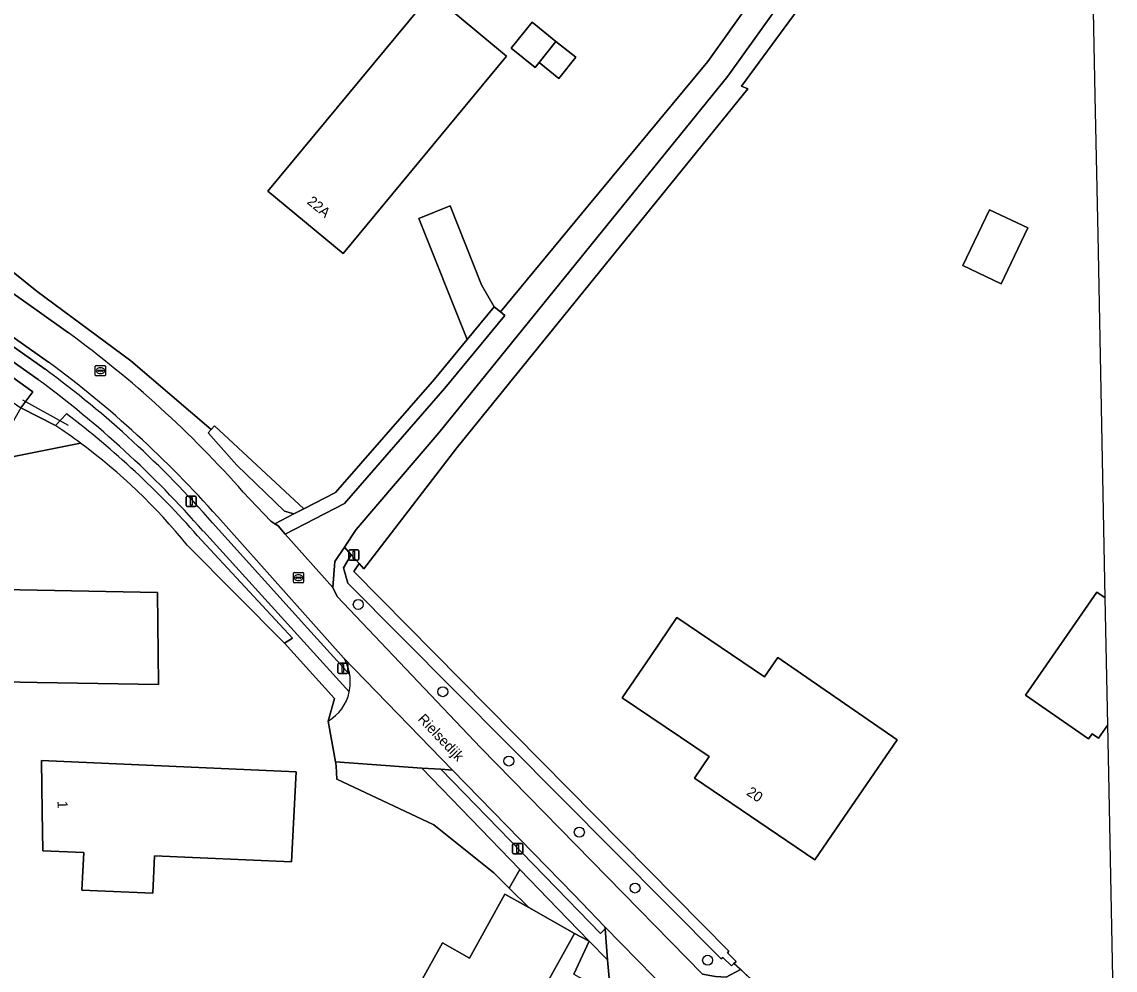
# Model space of a CAD drawing. Extents: x 163859 to 164644, y 379566 to 382155.
# Drawn here: x 164498.5 to 164605.3, y 381588.1 to 381680.8 of the extents above; entities that cross this region are included whole.
import ezdxf

# ---------------------------------------------------------------- set-up
doc = ezdxf.new("R2010")
doc.units = 0
for name, color, linetype in [('IMGEO_Boom', 7, 'Continuous'), ('IMGEO_Duiker', 7, 'Continuous'), ('IMGEO_Erf', 7, 'Continuous'), ('IMGEO_Fietspad_open', 7, 'Continuous'), ('IMGEO_Groenvoorziening', 7, 'Continuous'), ('IMGEO_Haag', 7, 'Continuous'), ('IMGEO_Lichtmast', 7, 'Continuous'), ('IMGEO_Loofbos', 7, 'Continuous'), ('IMGEO_Openbare_ruimte_label', 7, 'Continuous'), ('IMGEO_Pand', 7, 'Continuous'), ('IMGEO_Pand_nummerreeks', 7, 'Continuous'), ('IMGEO_Rijbaan_lokaal_gesloten', 7, 'Continuous'), ('IMGEO_Rijbaan_lokaal_halfverhard', 7, 'Continuous'), ('IMGEO_Rioolput', 7, 'Continuous'), ('IMGEO_Verkeersbordpaal', 7, 'Continuous'), ('IMGEO_Voetpad_open', 7, 'Continuous'), ('IMGEO_Waterloop', 7, 'Continuous')]:
    doc.layers.add(name, color=color, linetype=linetype)

msp = doc.modelspace()

# ---------------------------------------------------------------- linework, layer by layer
at = {"layer": 'IMGEO_Boom'}
for centre in [(164531.36, 381623.88), (164539.61, 381615.35), (164546.07, 381608.57), (164552.95, 381601.62), (164558.39, 381596.16), (164565.48, 381589.1)]:
    msp.add_circle(centre, 0.489, dxfattribs=at)
at = {"layer": 'IMGEO_Duiker'}
for points in [[(164503.07, 381641.38), (164498.6, 381643.85)], [(164571.59, 381585.44), (164568.07, 381588.81)]]:
    msp.add_lwpolyline(points, dxfattribs=at)
at = {"layer": 'IMGEO_Erf'}
for points in [[(164605.28, 381575.7), (164604.65, 381607.33), (164604.56, 381612.11), (164603.65, 381610.81), (164603.04, 381611.23), (164602.69, 381610.73), (164596.53, 381615), (164603.51, 381625.08), (164604.31, 381624.53), (164603.61, 381660.01), (164603.34, 381673.58), (164602.68, 381706.7)], [(164460.51, 381684.89), (164470.41, 381677.43), (164474.4, 381674.42), (164486.92, 381664.98), (164500, 381654.46), (164509.16, 381647.67), (164516.98, 381640.96), (164517.33, 381641.34), (164526.03, 381633.22), (164529.15, 381634.83), (164538.79, 381645.9), (164541.99, 381649.77), (164537.26, 381661.6), (164540.32, 381662.83), (164543.41, 381655.11), (164544.64, 381652.97), (164545.26, 381652.47), (164553.79, 381662.79), (164565.5, 381676.94), (164583.03, 381701.54)], [(164584.37, 381695.76), (164568.78, 381674.53), (164569.41, 381674.27), (164540.99, 381639.17), (164531.9, 381627.37), (164531.45, 381627.87), (164530.94, 381627.08), (164567.56, 381589.98), (164567.41, 381589.82), (164568.26, 381588.99), (164568.04, 381588.78), (164568.68, 381588.2), (164571.4, 381585.74)], [(164504.24, 381639.64), (164497.72, 381638.34), (164491.56, 381625.42), (164500, 381625.26), (164511.74, 381625.03), (164511.85, 381616.05), (164500, 381616.26), (164491.64, 381616.41), (164491.64, 381607.59), (164473.79, 381606.76), (164452.07, 381605.75)], [(164537.14, 381586.42), (164539.57, 381590.79), (164542.21, 381589.32), (164545.68, 381595.56), (164548.03, 381594.24), (164546.1, 381596.15), (164544.61, 381597.64), (164538.75, 381602.33), (164529.28, 381606.81), (164529.21, 381608.09), (164529.15, 381608.49), (164528.41, 381612.47), (164529.03, 381614.69), (164524.17, 381620.08), (164514.65, 381629.66)], [(164552.41, 381587.73), (164553.92, 381590.97), (164552.48, 381591.73), (164542.86, 381574.41)]]:
    msp.add_lwpolyline(points, dxfattribs=at)
for points in [[(164545.84, 381677.45), (164529.89, 381658.17), (164522.53, 381664.27), (164538.51, 381683.58)], [(164550.67, 381678.91), (164552.61, 381677.35), (164550.96, 381675.29), (164549.02, 381676.84), (164548.64, 381676.37), (164546.3, 381678.24), (164548.33, 381680.78)], [(164593.01, 381662.45), (164596.74, 381660.67), (164594.14, 381655.22), (164590.41, 381656.99)], [(164584, 381610.64), (164578.77, 381603.04), (164575.94, 381598.92), (164564.21, 381606.9), (164565.63, 381609), (164557.14, 381614.74), (164559.95, 381618.88), (164562.46, 381622.6), (164571.05, 381616.79), (164572.34, 381618.7)], [(164511.3, 381595.66), (164504.37, 381595.96), (164504.54, 381599.63), (164500.55, 381599.81), (164500.49, 381603.61), (164500.42, 381608.61), (164525.3, 381607.51), (164524.84, 381598.73), (164511.47, 381599.32)]]:
    msp.add_lwpolyline(points, close=True, dxfattribs=at)
msp.add_arc((164470.2, 381593.71), 57.17, 38.9591, 53.4562, dxfattribs=at)
at = {"layer": 'IMGEO_Fietspad_open'}
msp.add_lwpolyline([(164555.48, 381592.17), (164555.02, 381591.73), (164551.82, 381595.01), (164539.43, 381607.77), (164537.57, 381607.88), (164547.15, 381597.97), (164550.86, 381594.13), (164553.92, 381590.97), (164555.7, 381589.13)], close=True, dxfattribs=at)
at = {"layer": 'IMGEO_Groenvoorziening'}
for points in [[(164590.11, 381705.69), (164589.35, 381706.24), (164585.06, 381700.14), (164567.44, 381675.52), (164539.23, 381640.65), (164531.15, 381631.21), (164530, 381629.48), (164530.68, 381628.73), (164531.06, 381628.3), (164531.45, 381627.87), (164531.9, 381627.37), (164540.99, 381639.17), (164569.41, 381674.27), (164568.78, 381674.53), (164584.37, 381695.76), (164585.57, 381697.39), (164584.68, 381698)], [(164530, 381629.48), (164529.06, 381628.07), (164528.86, 381625.54), (164529.3, 381624.66), (164543.31, 381609.9), (164564.98, 381587.75), (164566.26, 381587.51), (164567.28, 381587.44), (164568.68, 381588.2), (164568.04, 381588.78), (164567.8, 381588.54), (164566.97, 381589.37), (164566.8, 381589.23), (164530.34, 381625.94), (164529.92, 381627.46), (164530.68, 381628.73)], [(164546.1, 381596.15), (164547.15, 381597.97), (164537.57, 381607.88), (164529.15, 381608.49), (164529.21, 381608.09), (164529.28, 381606.81), (164538.75, 381602.33), (164544.61, 381597.64)], [(164555.45, 381592.38), (164552.4, 381595.54), (164540.55, 381607.69), (164539.43, 381607.77), (164551.82, 381595.01), (164555.02, 381591.73), (164555.48, 381592.17)], [(164553.92, 381590.97), (164550.86, 381594.13), (164547.15, 381597.97), (164546.1, 381596.15), (164548.03, 381594.24), (164552.48, 381591.73)], [(164553.92, 381590.97), (164552.41, 381587.73), (164555.39, 381586.08), (164555.89, 381586.98), (164555.7, 381589.13)]]:
    msp.add_lwpolyline(points, close=True, dxfattribs=at)
for points in [[(164501.11, 381647.55), (164500, 381648.34), (164476.96, 381664.61), (164456.32, 381678.95), (164455.06, 381679.04), (164475.88, 381664.4), (164500, 381647.42), (164500.79, 381646.87)], [(164500.08, 381645.86), (164475.21, 381663.4), (164453.43, 381678.67)], [(164450.24, 381675.39), (164452.88, 381674.52), (164452.57, 381675.49), (164453.36, 381676.59), (164474.27, 381662.77), (164499.59, 381644.65), (164498.4, 381643.1), (164501.8, 381641.35), (164502.86, 381642.51)], [(164500, 381654.46), (164486.92, 381664.98), (164474.4, 381674.42), (164474.91, 381670.3), (164479.1, 381667.39), (164485.58, 381662.79), (164500, 381652.59), (164503.05, 381650.43)], [(164520.13, 381634.85), (164522.82, 381632.01), (164523.21, 381631.76), (164525.08, 381632.72), (164524.17, 381632.98), (164519.51, 381637.49), (164516.7, 381640.66), (164516.98, 381640.96), (164509.16, 381647.67), (164500, 381654.46)], [(164529.93, 381618.65), (164527, 381621.94), (164517.63, 381632.43)], [(164530.48, 381615.32), (164516.23, 381631.03)], [(164517.12, 381631.86), (164526.41, 381621.55), (164530.52, 381616.98)], [(164515.67, 381630.58), (164524.93, 381620.58), (164524.17, 381620.08), (164529.03, 381614.69), (164528.41, 381612.47)]]:
    msp.add_lwpolyline(points, dxfattribs=at)
for centre, radius, start, end in [((164440.03, 381564.16), 106.83, 41.429, 53.8516), ((164437.85, 381561.83), 106.54, 41.506, 53.5746), ((164438.25, 381562.31), 103.94, 41.3936, 53.5014), ((164438.41, 381562.58), 104.86, 41.3558, 53.4947), ((164450.37, 381573.34), 86.83, 41.2377, 52.812), ((164525.89, 381616.28), 4.69, 8.5904, 30.365), ((164526.31, 381616.18), 4.25, 299.5009, 348.3365)]:
    msp.add_arc(centre, radius, start, end, dxfattribs=at)
at = {"layer": 'IMGEO_Haag'}
for points in [[(164501.11, 381647.55), (164500, 381648.34), (164476.96, 381664.61), (164456.32, 381678.95), (164455.06, 381679.04), (164475.88, 381664.4), (164500, 381647.42), (164500.79, 381646.87)], [(164529.93, 381618.65), (164527, 381621.94), (164517.63, 381632.43)], [(164517.12, 381631.86), (164526.41, 381621.55), (164530.52, 381616.98)]]:
    msp.add_lwpolyline(points, dxfattribs=at)
msp.add_lwpolyline([(164555.45, 381592.38), (164552.4, 381595.54), (164540.55, 381607.69), (164539.43, 381607.77), (164551.82, 381595.01), (164555.02, 381591.73), (164555.48, 381592.17)], close=True, dxfattribs=at)
for centre, radius, start, end in [((164437.85, 381561.83), 106.54, 41.506, 53.5746), ((164438.41, 381562.58), 104.86, 41.3558, 53.4947), ((164525.89, 381616.28), 4.69, 8.5904, 30.365)]:
    msp.add_arc(centre, radius, start, end, dxfattribs=at)
at = {"layer": 'IMGEO_Lichtmast'}
for p, q in [((164514.55, 381633.55), (164514.55, 381634.35)), ((164514.55, 381634.35), (164514.55, 381633.55)), ((164514.65, 381634.45), (164515.44, 381634.45)), ((164515.44, 381634.45), (164514.65, 381634.45)), ((164515.54, 381634.35), (164515.54, 381633.55)), ((164515.54, 381633.55), (164515.54, 381634.35)), ((164515.44, 381633.45), (164514.65, 381633.45)), ((164514.65, 381633.45), (164515.44, 381633.45)), ((164529.46, 381618.12), (164530.25, 381618.12)), ((164530.25, 381618.12), (164529.46, 381618.12)), ((164529.36, 381617.22), (164529.36, 381618.02)), ((164529.36, 381618.02), (164529.36, 381617.22)), ((164530.25, 381617.12), (164529.46, 381617.12)), ((164529.46, 381617.12), (164530.25, 381617.12)), ((164530.35, 381618.02), (164530.35, 381617.22)), ((164530.35, 381617.22), (164530.35, 381618.02)), ((164546.43, 381599.6), (164546.43, 381600.4)), ((164546.43, 381600.4), (164546.43, 381599.6)), ((164546.53, 381600.5), (164547.32, 381600.5)), ((164547.32, 381600.5), (164546.53, 381600.5)), ((164547.42, 381600.4), (164547.42, 381599.6)), ((164547.42, 381599.6), (164547.42, 381600.4)), ((164547.32, 381599.5), (164546.53, 381599.5)), ((164546.53, 381599.5), (164547.32, 381599.5))]:
    msp.add_line(p, q, dxfattribs=at)
for points in [[(164514.97, 381634.32), (164515.12, 381634.32), (164515.12, 381633.57), (164514.97, 381633.57), (164514.97, 381634.32)], [(164529.78, 381618), (164529.93, 381618), (164529.93, 381617.25), (164529.78, 381617.25), (164529.78, 381618)], [(164546.85, 381600.38), (164547, 381600.38), (164547, 381599.63), (164546.85, 381599.63), (164546.85, 381600.38)]]:
    msp.add_lwpolyline(points, dxfattribs=at)
for centre, start, end in [((164514.65, 381634.35), 90, 180), ((164514.65, 381634.35), 90, 180), ((164515.44, 381634.35), 0, 90), ((164515.44, 381634.35), 360, 90), ((164514.65, 381633.55), 180, 270), ((164514.65, 381633.55), 180, 270), ((164515.44, 381633.55), 270, 0), ((164515.44, 381633.55), 270, 0), ((164529.46, 381618.02), 90, 180), ((164529.46, 381618.02), 90, 180), ((164530.25, 381618.02), 0, 90), ((164530.25, 381618.02), 360, 90), ((164529.46, 381617.22), 180, 270), ((164529.46, 381617.22), 180, 270), ((164530.25, 381617.22), 270, 0), ((164530.25, 381617.22), 270, 0), ((164546.53, 381600.4), 90, 180), ((164546.53, 381600.4), 90, 180), ((164547.32, 381600.4), 0, 90), ((164547.32, 381600.4), 360, 90), ((164546.53, 381599.6), 180, 270), ((164546.53, 381599.6), 180, 270), ((164547.32, 381599.6), 270, 0), ((164547.32, 381599.6), 270, 0)]:
    msp.add_arc(centre, 0.1, start, end, dxfattribs=at)
at = {"layer": 'IMGEO_Loofbos'}
msp.add_lwpolyline([(164501.8, 381641.35), (164498.4, 381643.1), (164483.66, 381617.04), (164473.55, 381613.91), (164473.69, 381609.8), (164473.79, 381606.76), (164491.64, 381607.59), (164491.64, 381616.41), (164491.56, 381625.42), (164497.72, 381638.34), (164504.24, 381639.64)], dxfattribs=at)
msp.add_arc((164470.8, 381594.55), 56.13, 53.4347, 56.4708, dxfattribs=at)
at = {"layer": 'IMGEO_Pand'}
for points in [[(164545.84, 381677.45), (164538.51, 381683.58), (164522.53, 381664.27), (164529.89, 381658.17)], [(164549.02, 381676.84), (164550.67, 381678.91), (164548.33, 381680.78), (164546.3, 381678.24), (164548.64, 381676.37)], [(164550.67, 381678.91), (164549.02, 381676.84), (164550.96, 381675.29), (164552.61, 381677.35)], [(164593.01, 381662.45), (164590.41, 381656.99), (164594.14, 381655.22), (164596.74, 381660.67)], [(164511.74, 381625.03), (164500, 381625.26), (164491.56, 381625.42), (164491.64, 381616.41), (164500, 381616.26), (164511.85, 381616.05)], [(164604.56, 381612.11), (164604.31, 381624.53), (164603.51, 381625.08), (164596.53, 381615), (164602.69, 381610.73), (164603.04, 381611.23), (164603.65, 381610.81)], [(164572.34, 381618.7), (164571.05, 381616.79), (164562.46, 381622.6), (164559.95, 381618.88), (164557.14, 381614.74), (164565.63, 381609), (164564.21, 381606.9), (164575.94, 381598.92), (164578.77, 381603.04), (164584, 381610.64)], [(164525.3, 381607.51), (164500.42, 381608.61), (164500.49, 381603.61), (164500.55, 381599.81), (164504.54, 381599.63), (164504.37, 381595.96), (164511.3, 381595.66), (164511.47, 381599.32), (164524.84, 381598.73)], [(164552.48, 381591.73), (164548.03, 381594.24), (164545.68, 381595.56), (164542.21, 381589.32), (164539.57, 381590.79), (164537.14, 381586.42), (164539.76, 381584.96), (164536.02, 381578.22), (164542.86, 381574.41)]]:
    msp.add_lwpolyline(points, close=True, dxfattribs=at)
at = {"layer": 'IMGEO_Rijbaan_lokaal_gesloten'}
for points in [[(164503.05, 381650.43), (164500, 381652.59), (164485.58, 381662.79), (164479.1, 381667.39), (164474.91, 381670.3), (164466.53, 381676.14), (164455.77, 381683.63), (164441.19, 381693.79), (164424.68, 381705.23)], [(164424.31, 381700.57), (164445.11, 381686.13), (164456.32, 381678.95), (164476.96, 381664.61), (164500, 381648.34), (164501.11, 381647.55)], [(164543.31, 381609.9), (164529.3, 381624.66), (164528.86, 381625.54), (164524.23, 381630.76), (164523.52, 381631.56), (164523.21, 381631.76), (164522.82, 381632.01), (164520.13, 381634.85)], [(164517.63, 381632.43), (164527, 381621.94), (164529.93, 381618.65), (164540.55, 381607.69), (164552.4, 381595.54), (164555.45, 381592.38), (164563.42, 381584.23)], [(164570.33, 381584.58), (164571.4, 381585.74), (164568.68, 381588.2), (164567.28, 381587.44), (164566.26, 381587.51), (164564.98, 381587.75), (164543.31, 381609.9)]]:
    msp.add_lwpolyline(points, dxfattribs=at)
for centre, radius, start, end in [((164440.03, 381564.16), 106.83, 41.429, 53.8516), ((164437.85, 381561.83), 106.54, 41.506, 53.5746)]:
    msp.add_arc(centre, radius, start, end, dxfattribs=at)
at = {"layer": 'IMGEO_Rijbaan_lokaal_halfverhard'}
msp.add_lwpolyline([(164567.44, 381675.52), (164585.06, 381700.14), (164583.03, 381701.54), (164565.5, 381676.94), (164553.79, 381662.79), (164545.26, 381652.47), (164545.68, 381652.11), (164539.82, 381645.02), (164530, 381633.75), (164524.23, 381630.76), (164528.86, 381625.54), (164529.06, 381628.07), (164530, 381629.48), (164531.15, 381631.21), (164539.23, 381640.65)], close=True, dxfattribs=at)
at = {"layer": 'IMGEO_Rioolput'}
for p, q in [((164505.67, 381646.29), (164505.67, 381647.15)), ((164505.75, 381647.22), (164506.6, 381647.22)), ((164506.16, 381647), (164506.19, 381647)), ((164506.68, 381647.15), (164506.68, 381646.29)), ((164506.6, 381646.22), (164505.75, 381646.22)), ((164505.93, 381646.71), (164505.93, 381646.73)), ((164506.37, 381646.68), (164505.97, 381646.68)), ((164505.98, 381646.76), (164506.37, 381646.76)), ((164506.18, 381646.44), (164506.16, 381646.44)), ((164506.42, 381646.73), (164506.42, 381646.71)), ((164525.02, 381626.07), (164525.02, 381626.92)), ((164525.09, 381626.99), (164525.95, 381626.99)), ((164525.51, 381626.77), (164525.53, 381626.77)), ((164526.02, 381626.92), (164526.02, 381626.07)), ((164525.95, 381625.99), (164525.09, 381625.99)), ((164525.28, 381626.49), (164525.28, 381626.5)), ((164525.32, 381626.54), (164525.72, 381626.54)), ((164525.72, 381626.45), (164525.32, 381626.45)), ((164525.53, 381626.21), (164525.5, 381626.21)), ((164525.76, 381626.5), (164525.76, 381626.49))]:
    msp.add_line(p, q, dxfattribs=at)
for points in [[(164505.67, 381646.29), (164505.67, 381647.15)], [(164505.75, 381647.22), (164506.6, 381647.22)], [(164506.68, 381647.15), (164506.68, 381646.29)], [(164506.6, 381646.22), (164505.75, 381646.22)], [(164525.02, 381626.07), (164525.02, 381626.92)], [(164525.09, 381626.99), (164525.95, 381626.99)], [(164526.02, 381626.92), (164526.02, 381626.07)], [(164525.95, 381625.99), (164525.09, 381625.99)]]:
    msp.add_lwpolyline(points, dxfattribs=at)
for centre, radius, start, end in [((164505.75, 381647.14), 0.0765, 91.552, 178.448), ((164505.75, 381647.14), 0.0765, 91.552, 178.448), ((164506.6, 381647.14), 0.0765, 1.552, 88.448), ((164506.6, 381647.14), 0.0765, 1.552, 88.448), ((164505.75, 381646.3), 0.0765, 181.552, 268.448), ((164505.75, 381646.3), 0.0765, 181.552, 268.448), ((164505.97, 381646.72), 0.0403, 85.8775, 175.7526), ((164505.97, 381646.71), 0.0366, 178.938, 274.7102), ((164506.38, 381646.72), 0.0386, 1.7309, 96.639), ((164506.37, 381646.72), 0.043, 264.8664, 352.4533), ((164506.6, 381646.3), 0.0765, 271.552, 358.448), ((164506.6, 381646.3), 0.0765, 271.552, 358.448), ((164525.1, 381626.92), 0.0765, 91.552, 178.448), ((164525.1, 381626.92), 0.0765, 91.552, 178.448), ((164525.94, 381626.92), 0.0765, 1.552, 88.448), ((164525.94, 381626.92), 0.0765, 1.552, 88.448), ((164525.1, 381626.07), 0.0765, 181.552, 268.448), ((164525.1, 381626.07), 0.0765, 181.552, 268.448), ((164525.32, 381626.5), 0.0403, 85.8775, 175.7526), ((164525.31, 381626.49), 0.0366, 178.938, 274.7102), ((164525.72, 381626.5), 0.0386, 1.7309, 96.639), ((164525.72, 381626.49), 0.043, 264.8664, 352.4533), ((164525.94, 381626.07), 0.0765, 271.552, 358.448), ((164525.94, 381626.07), 0.0765, 271.552, 358.448)]:
    msp.add_arc(centre, radius, start, end, dxfattribs=at)
for centre, major_axis, ratio, start_param, end_param in [((164506.16, 381646.72), (-0.387, 0.002), 0.722429, 4.712389, 7.853982), ((164506.19, 381646.72), (-0.39, 0.002), 0.717154, 1.570796, 4.712389), ((164525.51, 381626.49), (-0.387, 0.002), 0.722429, 4.712389, 7.853982), ((164525.53, 381626.49), (-0.39, 0.002), 0.717154, 1.570796, 4.712389)]:
    msp.add_ellipse(centre, major_axis=major_axis, ratio=ratio, start_param=start_param, end_param=end_param, dxfattribs=at)
at = {"layer": 'IMGEO_Verkeersbordpaal'}
for p, q in [((164530.43, 381628.3), (164530.43, 381629.1)), ((164530.43, 381629.1), (164530.43, 381628.3)), ((164530.53, 381629.2), (164531.32, 381629.2)), ((164531.32, 381629.2), (164530.53, 381629.2)), ((164531.42, 381629.1), (164531.42, 381628.3)), ((164531.42, 381628.3), (164531.42, 381629.1)), ((164531.32, 381628.2), (164530.53, 381628.2)), ((164530.53, 381628.2), (164531.32, 381628.2))]:
    msp.add_line(p, q, dxfattribs=at)
msp.add_lwpolyline([(164530.85, 381629.08), (164531, 381629.08), (164531, 381628.33), (164530.85, 381628.33), (164530.85, 381629.08)], dxfattribs=at)
for centre, start, end in [((164530.53, 381629.1), 90, 180), ((164530.53, 381629.1), 90, 180), ((164531.32, 381629.1), 0, 90), ((164531.32, 381629.1), 360, 90), ((164530.53, 381628.3), 180, 270), ((164530.53, 381628.3), 180, 270), ((164531.32, 381628.3), 270, 0), ((164531.32, 381628.3), 270, 0)]:
    msp.add_arc(centre, 0.1, start, end, dxfattribs=at)
at = {"layer": 'IMGEO_Voetpad_open'}
for points in [[(164500.79, 381646.87), (164500, 381647.42), (164475.88, 381664.4), (164455.06, 381679.04), (164453.43, 381678.67), (164475.21, 381663.4), (164500.08, 381645.86)], [(164516.23, 381631.03), (164530.48, 381615.32)], [(164530.52, 381616.98), (164526.41, 381621.55), (164517.12, 381631.86)], [(164528.41, 381612.47), (164529.15, 381608.49), (164537.57, 381607.88), (164539.43, 381607.77), (164540.55, 381607.69), (164529.93, 381618.65)]]:
    msp.add_lwpolyline(points, dxfattribs=at)
for points in [[(164540.32, 381662.83), (164537.26, 381661.6), (164541.99, 381649.77), (164544.64, 381652.97), (164543.41, 381655.11)], [(164545.26, 381652.47), (164544.64, 381652.97), (164541.99, 381649.77), (164538.79, 381645.9), (164529.15, 381634.83), (164526.03, 381633.22), (164525.08, 381632.72), (164523.21, 381631.76), (164523.52, 381631.56), (164524.23, 381630.76), (164530, 381633.75), (164539.82, 381645.02), (164545.68, 381652.11)], [(164559.1, 381581.86), (164559.18, 381581.91), (164559.29, 381581.99), (164559.42, 381582.05), (164559.55, 381582.1), (164559.65, 381582.14), (164561.55, 381583.1), (164562.4, 381584.01), (164563.42, 381584.23), (164555.45, 381592.38), (164555.48, 381592.17), (164555.7, 381589.13), (164555.89, 381586.98), (164555.39, 381586.08), (164554.8, 381585.02), (164552.46, 381580.72), (164551.03, 381575.5), (164550.63, 381574.07), (164551.01, 381573.92), (164549.26, 381569.31), (164552.89, 381568.16), (164552.95, 381568.37), (164553.97, 381571.68), (164556.81, 381580.58)]]:
    msp.add_lwpolyline(points, close=True, dxfattribs=at)
for centre, radius, start, end in [((164438.25, 381562.31), 103.94, 41.3936, 53.5014), ((164438.41, 381562.58), 104.86, 41.3558, 53.4947), ((164525.89, 381616.28), 4.69, 8.5904, 30.365), ((164525.91, 381616.28), 4.67, 348.0658, 8.6355), ((164525.91, 381616.28), 4.67, 348.0658, 8.6355), ((164526.31, 381616.18), 4.25, 299.5009, 348.3365)]:
    msp.add_arc(centre, radius, start, end, dxfattribs=at)
at = {"layer": 'IMGEO_Waterloop'}
for points in [[(164498.4, 381643.1), (164499.59, 381644.65), (164474.27, 381662.77), (164453.36, 381676.59), (164452.57, 381675.49), (164452.88, 381674.52)], [(164517.33, 381641.34), (164516.98, 381640.96), (164516.7, 381640.66), (164519.51, 381637.49), (164524.17, 381632.98), (164525.08, 381632.72), (164526.03, 381633.22)], [(164530.94, 381627.08), (164531.45, 381627.87), (164531.06, 381628.3), (164530.68, 381628.73), (164529.92, 381627.46), (164530.34, 381625.94), (164566.8, 381589.23), (164566.97, 381589.37), (164567.8, 381588.54), (164568.04, 381588.78), (164568.26, 381588.99), (164567.41, 381589.82), (164567.56, 381589.98)]]:
    msp.add_lwpolyline(points, close=True, dxfattribs=at)
for points in [[(164502.86, 381642.51), (164501.8, 381641.35)], [(164514.65, 381629.66), (164524.17, 381620.08), (164524.93, 381620.58), (164515.67, 381630.58)]]:
    msp.add_lwpolyline(points, dxfattribs=at)
for centre, radius, start, end in [((164450.37, 381573.34), 86.83, 41.2377, 52.812), ((164470.8, 381594.55), 56.13, 53.4347, 56.4708), ((164470.2, 381593.71), 57.17, 38.9591, 53.4562)]:
    msp.add_arc(centre, radius, start, end, dxfattribs=at)

# ---------------------------------------------------------------- texts
at = {"layer": 'IMGEO_Openbare_ruimte_label'}
msp.add_text('Rielsedijk', height=1, rotation=313.5416, dxfattribs=at).set_placement((164537.11, 381612.61))
at = {"layer": 'IMGEO_Pand_nummerreeks'}
for s, rotation, p in [('22A', 320.1565, (164526.28, 381663.12)), ('20', 325.5767, (164569.2, 381605.32)), ('1', 270.6702, (164501.98, 381604.67))]:
    msp.add_text(s, height=1, rotation=rotation, dxfattribs=at).set_placement(p)

doc.saveas('drawing.dxf')
